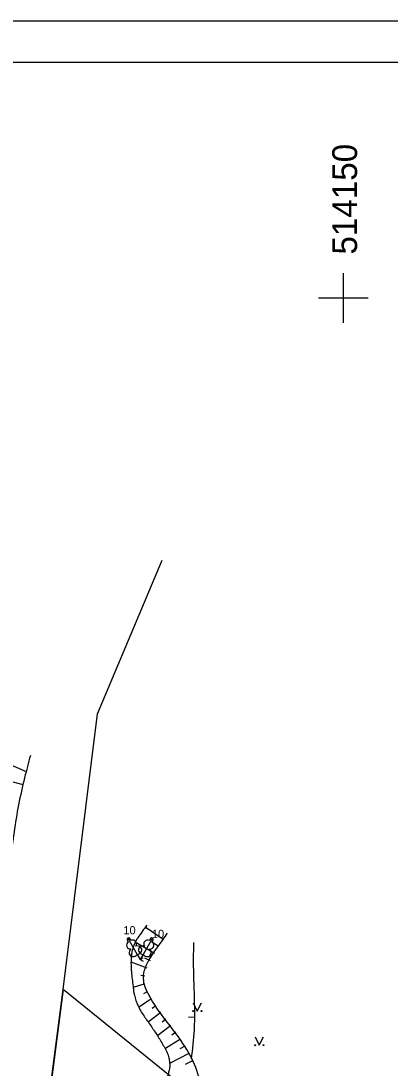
# Model space of a CAD drawing. Extents: x 514086 to 514457, y 297399 to 297567.
# Drawn here: x 514130.5 to 514152.8, y 297503.4 to 297566.8 of the extents above; entities that cross this region are included whole.
import ezdxf

# ---------------------------------------------------------------- set-up
doc = ezdxf.new("R2010")
doc.units = 0
for name, color, linetype in [('Level 1', 7, 'Continuous'), ('Level 23', 7, 'Continuous'), ('Level 29', 7, 'Continuous'), ('Level 30', 7, 'Continuous'), ('Level 31', 7, 'Continuous'), ('Level 32', 7, 'Continuous'), ('Level 36', 7, 'Continuous'), ('Level 46', 7, 'Continuous'), ('Level 63', 7, 'Continuous')]:
    doc.layers.add(name, color=color, linetype=linetype)

msp = doc.modelspace()

# ---------------------------------------------------------------- linework, layer by layer
at = {"layer": 'Level 1'}
for p, q in [((514137.539, 297510.292), (514137.712, 297509.991)), ((514137.885, 297510.292), (514137.712, 297509.991)), ((514137.712, 297509.991), (514137.885, 297510.091)), ((514137.712, 297509.991), (514137.885, 297509.891))]:
    msp.add_line(p, q, dxfattribs=at)
for points in [[(514136.962, 297511.29), (514137.539, 297510.292)], [(514137.156, 297511.134), (514137.154, 297511.134)], [(514138.462, 297511.29), (514137.885, 297510.292)], [(514138.423, 297511.044), (514138.423, 297511.045)]]:
    msp.add_lwpolyline(points, dxfattribs=at)
for centre, major_axis, ratio, start_param, end_param in [((514137.073, 297510.841), (0.073, -0.203), 0.861323, 3.141593, 6.283185), ((514137.037, 297511.16), (0.075, -0.13), 0.707107, 3.14537, 5.287485), ((514137.037, 297511.16), (0.075, -0.13), 0.707107, 0.995701, 3.137816), ((514137.296, 297510.969), (0.14, -0.165), 0.861323, 0, 3.141593), ((514137.493, 297510.549), (-0.313, -0.071), 0.814445, 1.531171, 4.712389), ((514137.931, 297510.549), (0.313, -0.071), 0.814445, 1.570796, 4.752015), ((514138.128, 297510.969), (-0.14, -0.165), 0.861323, 3.141593, 6.283185), ((514138.387, 297511.16), (-0.075, -0.13), 0.707107, 3.14537, 5.287485), ((514138.351, 297510.841), (-0.073, -0.203), 0.861323, 0, 3.141593), ((514138.387, 297511.16), (-0.075, -0.13), 0.707107, 0.995701, 3.137816), ((514137.338, 297510.46), (0.218, 0.236), 0.814445, 1.570796, 4.752015), ((514138.086, 297510.46), (-0.218, 0.236), 0.814445, 1.531171, 4.712389)]:
    msp.add_ellipse(centre, major_axis=major_axis, ratio=ratio, start_param=start_param, end_param=end_param, dxfattribs=at)
at = {"layer": 'Level 23'}
for p, q in [((514140.921, 297507.374), (514141.171, 297506.874)), ((514141.171, 297506.874), (514141.421, 297507.374)), ((514144.669, 297505.311), (514144.919, 297504.811)), ((514144.919, 297504.811), (514145.169, 297505.311))]:
    msp.add_line(p, q, dxfattribs=at)
for centre, radius in [((514140.92, 297506.874), 0.028), ((514141.42, 297506.874), 0.0263), ((514144.668, 297504.811), 0.028), ((514145.168, 297504.811), 0.0263)]:
    msp.add_circle(centre, radius, dxfattribs=at)
at = {"layer": 'Level 29'}
for p, q in [((514135.124, 297524.854), (514139.051, 297534.144)), ((514133.046, 297508.174), (514135.124, 297524.854)), ((514130.604, 297489.221), (514133.046, 297508.174)), ((514139.316, 297503.122), (514133.046, 297508.174))]:
    msp.add_line(p, q, dxfattribs=at)
at = {"layer": 'Level 30'}
for p, q in [((514150, 297551.5), (514150, 297550)), ((514148.5, 297550), (514150, 297550)), ((514150, 297550), (514150, 297548.5)), ((514150, 297550), (514151.5, 297550))]:
    msp.add_line(p, q, dxfattribs=at)
at = {"layer": 'Level 31'}
for p, q in [((514129.747, 297521.83), (514130.818, 297521.364)), ((514129.407, 297520.891), (514130.621, 297520.57)), ((514139.105, 297511.207), (514138.023, 297511.942)), ((514138.573, 297510.361), (514137.416, 297511.05)), ((514138.83, 297510.789), (514138.497, 297511.008)), ((514138.138, 297509.462), (514137.162, 297509.824)), ((514138.339, 297509.919), (514138.003, 297510.071)), ((514137.986, 297508.986), (514137.748, 297509.034)), ((514137.939, 297508.493), (514137.291, 297508.31)), ((514138.391, 297507.606), (514137.624, 297507.117)), ((514138.138, 297508.037), (514137.921, 297507.913)), ((514138.67, 297507.191), (514138.438, 297507.028)), ((514138.968, 297506.789), (514138.201, 297506.195)), ((514139.274, 297506.394), (514139.039, 297506.212)), ((514139.578, 297505.997), (514138.772, 297505.383)), ((514140.158, 297505.183), (514139.237, 297504.606)), ((514139.879, 297505.598), (514139.621, 297505.418)), ((514140.414, 297504.754), (514140.111, 297504.584)), ((514140.648, 297504.312), (514139.498, 297503.708)), ((514140.881, 297503.87), (514140.44, 297503.638))]:
    msp.add_line(p, q, dxfattribs=at)
msp.add_spline([(514139.853, 297497.778), (514140.258, 297498.576), (514141.401, 297501.745), (514140.437, 297504.714), (514138.22, 297507.891), (514137.927, 297508.692), (514139.101, 297511.202), (514139.369, 297511.596)], degree=3, dxfattribs=at)
at = {"layer": 'Level 32'}
msp.add_line((514141.035, 297506.491), (514140.635, 297506.517), dxfattribs=at)
msp.add_spline([(514140.824, 297503.986), (514140.992, 297505.748), (514140.946, 297510.145), (514140.969, 297511.029)], degree=3, dxfattribs=at)
at = {"layer": 'Level 36'}
for points in [[(514131.069, 297522.336), (514130.722, 297520.99), (514130.356, 297519.354), (514130.081, 297517.7), (514129.695, 297514.358), (514129.609, 297513.521), (514129.528, 297512.683), (514129.446, 297511.845), (514129.358, 297511.007), (514129.012, 297508.513), (514128.862, 297507.689), (514128.576, 297506.54), (514128.226, 297505.404), (514127.889, 297504.265), (514127.644, 297503.107), (514127.563, 297502.554)], [(514138.109, 297512.063), (514137.564, 297511.301), (514137.455, 297511.127), (514137.365, 297510.942), (514137.294, 297510.748), (514137.238, 297510.546), (514137.169, 297510.117), (514137.16, 297509.688), (514137.226, 297508.808), (514137.281, 297508.385), (514137.333, 297507.988), (514137.505, 297507.371), (514137.643, 297507.078), (514137.803, 297506.795), (514138.001, 297506.491), (514138.209, 297506.197), (514138.418, 297505.904), (514138.619, 297505.606), (514138.984, 297505.024), (514139.157, 297504.727), (514139.322, 297504.419), (514139.43, 297504.13), (514139.463, 297503.98), (514139.488, 297503.828), (514139.5, 297503.533), (514139.454, 297503.238), (514139.378, 297502.987), (514139.293, 297502.742), (514139.196, 297502.503), (514139.084, 297502.27), (514138.565, 297501.307), (514138.028, 297500.342), (514137.601, 297499.365), (514137.39, 297498.735)]]:
    msp.add_spline(points, degree=3, dxfattribs=at)
at = {"layer": 'Level 46'}
msp.add_lwpolyline([(514139.134, 297486.37), (514229.261, 297420.493), (514237.863, 297414.208), (514250.009, 297428.181), (514295.433, 297494.723), (514312.775, 297524.542), (514316.491, 297528.738), (514320.446, 297531.016), (514328.236, 297532.215), (514332.539, 297530.572), (514332.631, 297530.536), (514341.642, 297542.18), (514320.211, 297553.997), (514285.885, 297496.27), (514243.195, 297433.696), (514241.534, 297432.407), (514239.451, 297432.203), (514209.969, 297445.237), (514194.45, 297457.413), (514175.859, 297473.677), (514139.316, 297503.122), (514133.046, 297508.174), (514130.604, 297489.221)], close=True, dxfattribs=at)
at = {"layer": 'Level 63'}
for p, q in [((514086.037, 297566.752), (514457.195, 297566.752)), ((514096.037, 297564.252), (514454.695, 297564.252))]:
    msp.add_line(p, q, dxfattribs=at)

# ---------------------------------------------------------------- texts
at = {"layer": 'Level 1'}
for p in [(514136.512, 297511.515), (514138.237, 297511.29)]:
    msp.add_text(' 10', height=0.5, dxfattribs=at).set_placement(p)
at = {"layer": 'Level 30'}
msp.add_text('514150', height=1.5, rotation=90, dxfattribs=at).set_placement((514150.838, 297552.625))

doc.saveas('drawing.dxf')
